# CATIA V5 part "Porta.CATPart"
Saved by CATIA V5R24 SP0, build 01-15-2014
Part number: Porta
Bounding box of the stored display mesh (mm): x 0 to 3, y -65 to 65, z -152.5 to 152.5
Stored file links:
  C:\Users\Fatec\Desktop\Maquina componentes catia\Porta.CATPart
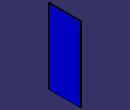
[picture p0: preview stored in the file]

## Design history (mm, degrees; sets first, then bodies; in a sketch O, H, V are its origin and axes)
Body1 (main body)
  Sketch1 on yz-plane, origin (0, 0, 0), H (0, 1, 0), V (0, 0, 1)
    line L1 (-65, 152.5) -> (65, 152.5)
    line L2 (65, 152.5) -> (65, -152.5)
    line L3 (65, -152.5) -> (-65, -152.5)
    line L4 (-65, -152.5) -> (-65, 152.5)
    length L4 = 305
    length L3 = 130
    horizontal: L1 H, L3 H
    vertical: L2 V, L4 V
    symmetry: L4 L2 V, L3 L1 H
  Pad1: profile Sketch1, direction (1, 0, 0), length 3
